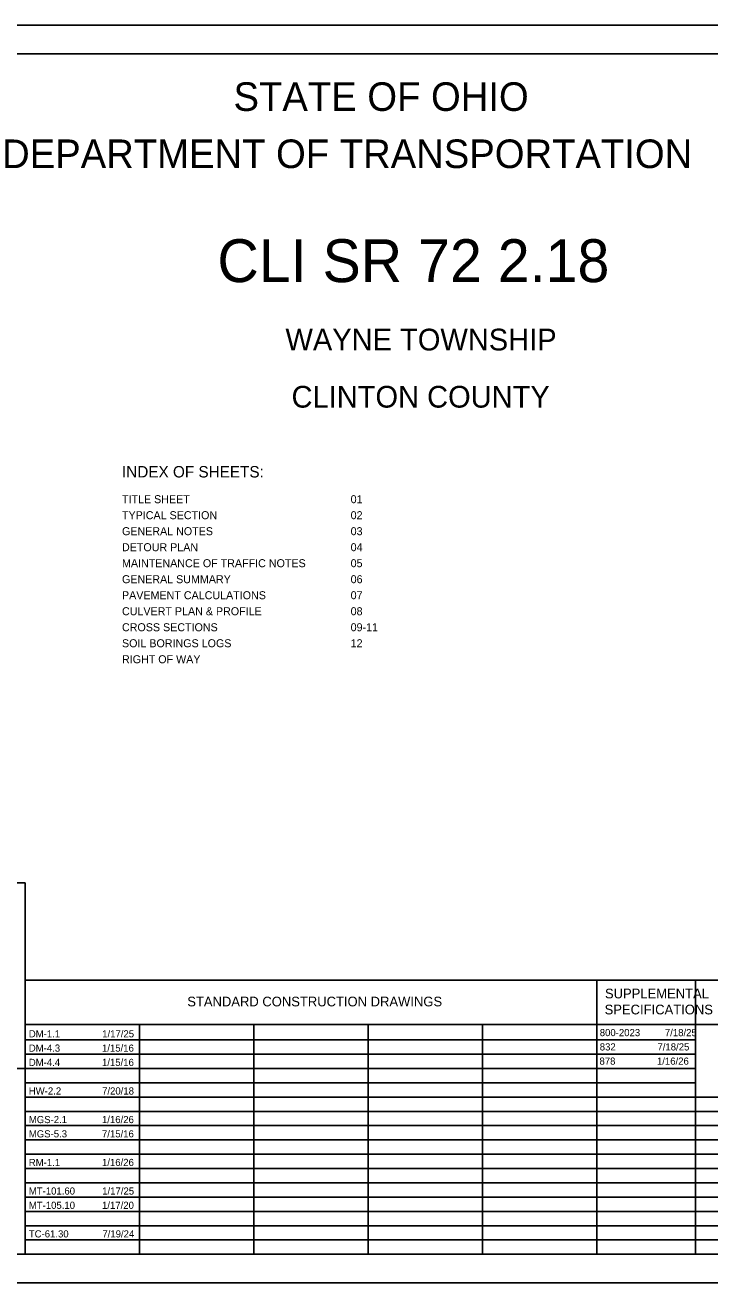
# Model space of a CAD drawing. Extents: x 0 to 34, y 0 to 22.
# Drawn here: x 10.15 to 22.13, y 0 to 22 of the extents above; entities that cross this region are included whole.
import ezdxf

# ---------------------------------------------------------------- set-up
doc = ezdxf.new("R2010")
doc.units = 0
for name, color, linetype in [('SH_Border', 7, 'Continuous'), ('SH_Cut_Line', 7, 'Continuous'), ('SH_Data', 7, 'Continuous'), ('SH_Text', 7, 'Continuous')]:
    doc.layers.add(name, color=color, linetype=linetype)

msp = doc.modelspace()

# ---------------------------------------------------------------- linework, layer by layer
at = {"layer": 'SH_Border'}
msp.add_lwpolyline([(1.5, 21.5), (33.5, 21.5), (33.5, 0.5), (1.5, 0.5)], close=True, dxfattribs=at)
at = {"layer": 'SH_Cut_Line'}
msp.add_lwpolyline([(0, 0), (34, 0), (34, 22), (0, 22)], close=True, dxfattribs=at)
at = {"layer": 'SH_Data'}
for p, q in [((10.15, 5.292), (23.6, 5.292)), ((10.15, 0.5), (10.15, 5.292)), ((20.15, 0.5), (20.15, 5.292)), ((21.875, 0.5), (21.875, 5.292)), ((10.15, 4.521), (23.6, 4.521)), ((12.15, 0.5), (12.15, 4.521)), ((14.15, 0.5), (14.15, 4.521)), ((16.15, 0.5), (16.15, 4.521)), ((18.15, 0.5), (18.15, 4.521)), ((10.15, 4.25), (21.875, 4.25)), ((10.15, 4), (21.875, 4)), ((10.15, 3.75), (21.875, 3.75)), ((10.15, 3.5), (21.875, 3.5)), ((10.15, 3.25), (23.6, 3.25)), ((10.15, 3), (23.6, 3)), ((10.15, 2.75), (23.6, 2.75)), ((10.15, 2.5), (23.6, 2.5)), ((10.15, 2.25), (23.6, 2.25)), ((10.15, 2), (23.6, 2)), ((10.15, 1.75), (23.6, 1.75)), ((10.15, 1.5), (23.6, 1.5)), ((10.15, 1.25), (23.6, 1.25)), ((10.15, 1), (23.6, 1)), ((10.15, 0.75), (23.6, 0.75))]:
    msp.add_line(p, q, dxfattribs=at)
for points in [[(10.15, 7), (7.35, 7), (7.35, 3.75), (10.15, 3.75)], [(10.15, 3.75), (7.35, 3.75), (7.35, 0.5), (10.15, 0.5)]]:
    msp.add_lwpolyline(points, close=True, dxfattribs=at)

# ---------------------------------------------------------------- texts
at = {"layer": 'SH_Text'}
for s, height, p in [('STATE OF OHIO', 0.5, (13.795, 20.5)), ('DEPARTMENT OF TRANSPORTATION', 0.5, (9.747, 19.5)), ('CLI SR 72 2.18', 0.75, (13.513, 17.505)), ('WAYNE TOWNSHIP', 0.38, (14.704, 16.31)), ('CLINTON COUNTY', 0.38, (14.81, 15.31)), ('INDEX OF SHEETS:', 0.2, (11.844, 14.088)), ('TITLE SHEET', 0.14, (11.844, 13.638)), ('01', 0.14, (15.844, 13.638)), ('TYPICAL SECTION', 0.14, (11.844, 13.358)), ('02', 0.14, (15.844, 13.358)), ('GENERAL NOTES', 0.14, (11.844, 13.078)), ('03', 0.14, (15.844, 13.078)), ('DETOUR PLAN', 0.14, (11.844, 12.798)), ('04', 0.14, (15.844, 12.798)), ('MAINTENANCE OF TRAFFIC NOTES', 0.14, (11.844, 12.518)), ('05', 0.14, (15.844, 12.518)), ('GENERAL SUMMARY', 0.14, (11.844, 12.238)), ('06', 0.14, (15.844, 12.238)), ('PAVEMENT CALCULATIONS', 0.14, (11.844, 11.958)), ('07', 0.14, (15.844, 11.958)), ('CULVERT PLAN & PROFILE', 0.14, (11.844, 11.678)), ('08', 0.14, (15.844, 11.678)), ('CROSS SECTIONS', 0.14, (11.844, 11.398)), ('09-11', 0.14, (15.844, 11.398)), ('SOIL BORINGS LOGS', 0.14, (11.844, 11.118)), ('12', 0.14, (15.844, 11.118)), ('RIGHT OF WAY', 0.14, (11.844, 10.838)), ('SUPPLEMENTAL', 0.17, (20.293, 4.976)), ('STANDARD CONSTRUCTION DRAWINGS', 0.17, (12.986, 4.836)), ('SPECIFICATIONS', 0.17, (20.287, 4.696)), ('DM-1.1', 0.125, (10.214, 4.294)), ('1/17/25', 0.125, (11.498, 4.294)), ('800-2023', 0.125, (20.202, 4.315)), ('7/18/25', 0.125, (21.341, 4.315)), ('832', 0.125, (20.202, 4.065)), ('7/18/25', 0.125, (21.211, 4.065)), ('DM-4.3', 0.125, (10.214, 4.044)), ('1/15/16', 0.125, (11.494, 4.044)), ('DM-4.4', 0.125, (10.214, 3.794)), ('1/15/16', 0.125, (11.494, 3.794)), ('878', 0.125, (20.197, 3.816)), ('1/16/26', 0.125, (21.202, 3.816)), ('HW-2.2', 0.125, (10.214, 3.294)), ('7/20/18', 0.125, (11.496, 3.294)), ('MGS-2.1', 0.125, (10.214, 2.794)), ('1/16/26', 0.125, (11.494, 2.794)), ('MGS-5.3', 0.125, (10.214, 2.544)), ('7/15/16', 0.125, (11.494, 2.544)), ('RM-1.1', 0.125, (10.214, 2.044)), ('1/16/26', 0.125, (11.494, 2.044)), ('MT-101.60', 0.125, (10.214, 1.544)), ('1/17/25', 0.125, (11.498, 1.544)), ('MT-105.10', 0.125, (10.214, 1.294)), ('1/17/20', 0.125, (11.495, 1.294)), ('TC-61.30', 0.125, (10.214, 0.794)), ('7/19/24', 0.125, (11.501, 0.794))]:
    msp.add_text(s, height=height, dxfattribs=at).set_placement(p)

doc.saveas('drawing.dxf')
